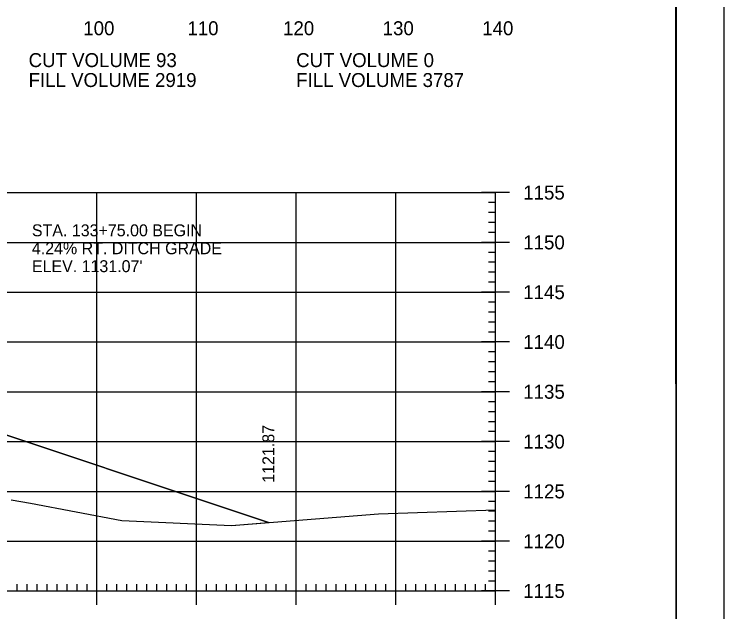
# Model space of a CAD drawing. Extents: x 1322838 to 1324533, y 339903 to 351025.
# Drawn here: x 1323795.4 to 1323866.6, y 342119.4 to 342179.4 of the extents above; entities that cross this region are included whole.
import ezdxf

# ---------------------------------------------------------------- set-up
doc = ezdxf.new("R2010")
doc.units = 0
for name, color, linetype in [('R_Axis', 7, 'Continuous'), ('R_Axis Annot', 7, 'Continuous'), ('R_Border', 7, 'Continuous'), ('R_Drive', 7, 'Continuous'), ('R_Exist Surface', 7, 'Continuous'), ('R_Fin Surface', 7, 'Continuous'), ('R_Fin Surface Annot', 7, 'Continuous'), ('R_Grid', 7, 'Continuous'), ('R_No Plot', 7, 'Continuous')]:
    doc.layers.add(name, color=color, linetype=linetype)

msp = doc.modelspace()

# ---------------------------------------------------------------- linework, layer by layer
at = {"layer": 'R_Axis'}
for p, q in [((1323845.115, 342161.482), (1323842.315, 342161.482)), ((1323843.715, 342121.482), (1323843.715, 342161.482)), ((1323843.715, 342160.482), (1323843.015, 342160.482)), ((1323843.715, 342159.482), (1323843.015, 342159.482)), ((1323843.715, 342158.482), (1323843.015, 342158.482)), ((1323843.715, 342157.482), (1323843.015, 342157.482)), ((1323845.115, 342156.482), (1323842.315, 342156.482)), ((1323843.715, 342155.482), (1323843.015, 342155.482)), ((1323843.715, 342154.482), (1323843.015, 342154.482)), ((1323843.715, 342153.482), (1323843.015, 342153.482)), ((1323843.715, 342152.482), (1323843.015, 342152.482)), ((1323845.115, 342151.482), (1323842.315, 342151.482)), ((1323843.715, 342150.482), (1323843.015, 342150.482)), ((1323843.715, 342149.482), (1323843.015, 342149.482)), ((1323843.715, 342148.482), (1323843.015, 342148.482)), ((1323843.715, 342147.482), (1323843.015, 342147.482)), ((1323845.115, 342146.482), (1323842.315, 342146.482)), ((1323843.715, 342145.482), (1323843.015, 342145.482)), ((1323843.715, 342144.482), (1323843.015, 342144.482)), ((1323843.715, 342143.482), (1323843.015, 342143.482)), ((1323843.715, 342142.482), (1323843.015, 342142.482)), ((1323845.115, 342141.482), (1323842.315, 342141.482)), ((1323843.715, 342140.482), (1323843.015, 342140.482)), ((1323843.715, 342139.482), (1323843.015, 342139.482)), ((1323843.715, 342138.482), (1323843.015, 342138.482)), ((1323843.715, 342137.482), (1323843.015, 342137.482)), ((1323845.115, 342136.482), (1323842.315, 342136.482)), ((1323843.715, 342135.482), (1323843.015, 342135.482)), ((1323843.715, 342134.482), (1323843.015, 342134.482)), ((1323843.715, 342133.482), (1323843.015, 342133.482)), ((1323843.715, 342132.482), (1323843.015, 342132.482)), ((1323845.115, 342131.482), (1323842.315, 342131.482)), ((1323843.715, 342130.482), (1323843.015, 342130.482)), ((1323843.715, 342129.482), (1323843.015, 342129.482)), ((1323843.715, 342128.482), (1323843.015, 342128.482)), ((1323843.715, 342127.482), (1323843.015, 342127.482)), ((1323845.115, 342126.482), (1323842.315, 342126.482)), ((1323843.715, 342125.482), (1323843.015, 342125.482)), ((1323843.715, 342124.482), (1323843.015, 342124.482)), ((1323843.715, 342123.482), (1323843.015, 342123.482)), ((1323803.715, 342120.082), (1323803.715, 342122.882)), ((1323813.715, 342120.082), (1323813.715, 342122.882)), ((1323823.715, 342120.082), (1323823.715, 342122.882)), ((1323833.715, 342120.082), (1323833.715, 342122.882)), ((1323843.715, 342120.082), (1323843.715, 342122.882)), ((1323795.715, 342121.482), (1323795.715, 342122.182)), ((1323796.715, 342121.482), (1323796.715, 342122.182)), ((1323797.715, 342121.482), (1323797.715, 342122.182)), ((1323798.715, 342121.482), (1323798.715, 342122.182)), ((1323799.715, 342121.482), (1323799.715, 342122.182)), ((1323800.715, 342121.482), (1323800.715, 342122.182)), ((1323801.715, 342121.482), (1323801.715, 342122.182)), ((1323802.715, 342121.482), (1323802.715, 342122.182)), ((1323804.715, 342121.482), (1323804.715, 342122.182)), ((1323805.715, 342121.482), (1323805.715, 342122.182)), ((1323806.715, 342121.482), (1323806.715, 342122.182)), ((1323807.715, 342121.482), (1323807.715, 342122.182)), ((1323808.715, 342121.482), (1323808.715, 342122.182)), ((1323809.715, 342121.482), (1323809.715, 342122.182)), ((1323810.715, 342121.482), (1323810.715, 342122.182)), ((1323811.715, 342121.482), (1323811.715, 342122.182)), ((1323812.715, 342121.482), (1323812.715, 342122.182)), ((1323814.715, 342121.482), (1323814.715, 342122.182)), ((1323815.715, 342121.482), (1323815.715, 342122.182)), ((1323816.715, 342121.482), (1323816.715, 342122.182)), ((1323817.715, 342121.482), (1323817.715, 342122.182)), ((1323818.715, 342121.482), (1323818.715, 342122.182)), ((1323819.715, 342121.482), (1323819.715, 342122.182)), ((1323820.715, 342121.482), (1323820.715, 342122.182)), ((1323821.715, 342121.482), (1323821.715, 342122.182)), ((1323822.715, 342121.482), (1323822.715, 342122.182)), ((1323824.715, 342121.482), (1323824.715, 342122.182)), ((1323825.715, 342121.482), (1323825.715, 342122.182)), ((1323826.715, 342121.482), (1323826.715, 342122.182)), ((1323827.715, 342121.482), (1323827.715, 342122.182)), ((1323828.715, 342121.482), (1323828.715, 342122.182)), ((1323829.715, 342121.482), (1323829.715, 342122.182)), ((1323830.715, 342121.482), (1323830.715, 342122.182)), ((1323831.715, 342121.482), (1323831.715, 342122.182)), ((1323832.715, 342121.482), (1323832.715, 342122.182)), ((1323834.715, 342121.482), (1323834.715, 342122.182)), ((1323835.715, 342121.482), (1323835.715, 342122.182)), ((1323836.715, 342121.482), (1323836.715, 342122.182)), ((1323837.715, 342121.482), (1323837.715, 342122.182)), ((1323838.715, 342121.482), (1323838.715, 342122.182)), ((1323839.715, 342121.482), (1323839.715, 342122.182)), ((1323840.715, 342121.482), (1323840.715, 342122.182)), ((1323841.715, 342121.482), (1323841.715, 342122.182)), ((1323842.715, 342121.482), (1323842.715, 342122.182)), ((1323843.715, 342122.482), (1323843.015, 342122.482)), ((1323563.715, 342121.482), (1323843.715, 342121.482)), ((1323845.115, 342121.482), (1323842.315, 342121.482))]:
    msp.add_line(p, q, dxfattribs=at)
at = {"layer": 'R_Border'}
msp.add_line((1323861.895, 342040.482), (1323861.895, 342245.942), dxfattribs=at)
at = {"layer": 'R_Exist Surface'}
msp.add_lwpolyline([(1323795.098, 342130.627), (1323797.056, 342130.293), (1323806.22, 342128.561), (1323817.233, 342128.062), (1323831.967, 342129.215), (1323843.715, 342129.629)], dxfattribs=at)
at = {"layer": 'R_Fin Surface'}
msp.add_lwpolyline([(1323603.856, 342143.89), (1323603.857, 342143.89), (1323618.491, 342139.011), (1323618.493, 342139.012), (1323640.081, 342146.208), (1323644.215, 342147.586), (1323648.839, 342148.742), (1323661.12, 342151.812), (1323666.215, 342153.086), (1323672.215, 342153.326), (1323673.933, 342153.361), (1323674.215, 342153.366), (1323690.453, 342153.691), (1323703.715, 342153.956), (1323733.216, 342153.366), (1323735.216, 342153.326), (1323741.216, 342153.086), (1323743.401, 342152.54), (1323746.312, 342151.812), (1323751.428, 342150.533), (1323763.216, 342147.586), (1323788.196, 342139.264), (1323820.924, 342128.35)], dxfattribs=at)
at = {"layer": 'R_Grid'}
for p, q in [((1323563.715, 342161.482), (1323843.715, 342161.482)), ((1323803.715, 342121.482), (1323803.715, 342161.482)), ((1323813.715, 342121.482), (1323813.715, 342161.482)), ((1323823.715, 342121.482), (1323823.715, 342161.482)), ((1323833.715, 342121.482), (1323833.715, 342161.482)), ((1323843.715, 342121.482), (1323843.715, 342161.482)), ((1323563.715, 342156.482), (1323843.715, 342156.482)), ((1323563.715, 342151.482), (1323843.715, 342151.482)), ((1323563.715, 342146.482), (1323843.715, 342146.482)), ((1323563.715, 342141.482), (1323843.715, 342141.482)), ((1323563.715, 342136.482), (1323843.715, 342136.482)), ((1323563.715, 342131.482), (1323843.715, 342131.482)), ((1323563.715, 342126.482), (1323843.715, 342126.482)), ((1323563.715, 342121.482), (1323843.715, 342121.482))]:
    msp.add_line(p, q, dxfattribs=at)
at = {"layer": 'R_No Plot'}
for points in [[(1323533.308, 342249.837), (1323866.648, 342249.837), (1323866.648, 342036.499), (1323533.308, 342036.499)], [(1323779.635, 342245.942), (1323799.255, 342245.942), (1323799.255, 342236.062), (1323815.368, 342236.062), (1323838.567, 342236.062), (1323838.567, 342203.392), (1323861.775, 342203.392), (1323861.895, 342040.482), (1323545.715, 342040.482), (1323545.715, 342245.942)]]:
    msp.add_lwpolyline(points, close=True, dxfattribs=at)
msp.add_lwpolyline([(1323795.098, 342130.627), (1323797.056, 342130.293), (1323806.22, 342128.561), (1323817.233, 342128.062), (1323820.924, 342128.35), (1323788.196, 342139.264)], dxfattribs=at)

# ---------------------------------------------------------------- texts
at = {"layer": 'R_Axis Annot'}
for s, p in [('100', (1323802.343, 342177.282)), ('110', (1323812.795, 342177.282)), ('120', (1323822.398, 342177.282)), ('130', (1323832.398, 342177.282)), ('140', (1323842.398, 342177.282)), ('CUT VOLUME 93', (1323796.852, 342174.082)), ('CUT VOLUME 0', (1323823.715, 342174.082)), ('FILL VOLUME 2919', (1323796.852, 342172.082)), ('FILL VOLUME 3787', (1323823.715, 342172.082)), ('1155', (1323846.515, 342160.782)), ('1150', (1323846.515, 342155.782)), ('1145', (1323846.515, 342150.782)), ('1140', (1323846.515, 342145.782)), ('1135', (1323846.515, 342140.782)), ('1130', (1323846.515, 342135.782)), ('1125', (1323846.515, 342130.782)), ('1120', (1323846.515, 342125.782)), ('1115', (1323846.515, 342120.782))]:
    msp.add_text(s, height=1.4, dxfattribs=at).set_placement(p)
at = {"layer": 'R_Drive'}
for s, p in [('STA. 133+75.00 BEGIN', (1323797.18, 342157.093)), ('4.24% RT. DITCH GRADE', (1323797.18, 342155.293)), ("ELEV. 1131.07'", (1323797.18, 342153.493))]:
    msp.add_text(s, height=1.2, dxfattribs=at).set_placement(p)
at = {"layer": 'R_Fin Surface Annot'}
msp.add_text('1121.87', height=1.2, rotation=90, dxfattribs=at).set_placement((1323821.523, 342132.35))

doc.saveas('drawing.dxf')
